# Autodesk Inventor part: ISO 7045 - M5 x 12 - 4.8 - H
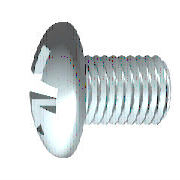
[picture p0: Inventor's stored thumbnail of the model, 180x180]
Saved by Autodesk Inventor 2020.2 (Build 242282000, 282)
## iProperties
Manager: www.cadconsulting.pl
Company: Fabian Stasiak CAD Consulting
Created: 2013-02
Part Number: ISO 7045 - M5 x 12 - 4.8 - H
Material: Stal nierdzewna 440C
Description: Śruba z łbem walcowym wypukłym z wgłębieniem krzyżowym
Document SubType Name: Modeling
Standard: ISO 7045
Designer: F.Stasiak
Standard Revision: 1994
Standards Organization: DIN
Language: pl-PL
Size Designation: M5 x 12 - 4.8 - H
Categories: <MemberInstance><Categories><Category DisplayName="Mocowania" InternalName="e4da775c-781d-43d5-af7c-5136215cf5a6" Mnemonic="FSTN"><Category DisplayName="Śruby"
Density: 7.75 g/cm^3
Appearance: Częściowo polerowana
IsCustomPart: 0
Author: F.Stasiak
Subject: Zbiór ćwiczeń. Autodesk Inventor 2020. Kurs podstawowy
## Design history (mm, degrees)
workplane "Work Plane3"
sketch "Szkic2"
  geometry: L1 (-6.543, 0)-(6.543, 0) reference; L2 (0, -6.543)-(0, 6.543) reference; L3 (0, 2.45)-(0, 0); L4 (0, 0)-(2.45, 0); L5 (0, 0)-(3.305, 3.305); L6 (0.415, 2.415)-(0.426, 0.744); L7 (2.415, 0.415)-(0.744, 0.426); L8 (0.415, -2.415)-(0.426, -0.744); L9 (2.415, -0.415)-(0.744, -0.426); L10 (-0.415, 2.415)-(-0.426, 0.744); L11 (-2.415, 0.415)-(-0.744, 0.426); L12 (-2.415, -0.415)-(-0.744, -0.426); L13 (-0.415, -2.415)-(-0.426, -0.744); A1 r 0.735 centre (0, 0) between (0.735, 0) and (0, 0.735); A2 r 2.45 centre (0, 0) between (2.45, 0) and (2.415, 0.415); A3 r 2.45 centre (0, 0) between (0.415, 2.415) and (0, 2.45); A4 r 2.45 centre (0, 0) between (2.415, 0.415) and (0.415, 2.415); A5 r 2.45 centre (0, 0) between (0, -2.45) and (0.415, -2.415); A6 r 2.45 centre (0, 0) between (0.415, -2.415) and (2.415, -0.415); A7 r 2.45 centre (0, 0) between (2.415, -0.415) and (2.45, 0); A8 r 2.45 centre (0, 0) between (-2.415, 0.415) and (-2.45, 0); A9 r 2.45 centre (0, 0) between (-0.415, 2.415) and (-2.415, 0.415); A10 r 2.45 centre (0, 0) between (0, 2.45) and (-0.415, 2.415); A11 r 2.45 centre (0, 0) between (-2.45, 0) and (-2.415, -0.415); A12 r 2.45 centre (0, 0) between (-2.415, -0.415) and (-0.415, -2.415); A13 r 2.45 centre (0, 0) between (-0.415, -2.415) and (0, -2.45); A14 r 0.858 centre (0, 0) between (0.858, 0) and (0, 0.858); A15 r 0.321 centre (0.746, 0.746) between (0.426, 0.744) and (0.744, 0.426); A16 r 0.321 centre (0.746, -0.746) between (0.744, -0.426) and (0.426, -0.744); A17 r 0.321 centre (-0.746, 0.746) between (-0.744, 0.426) and (-0.426, 0.744); A18 r 0.321 centre (-0.746, -0.746) between (-0.426, -0.744) and (-0.744, -0.426); 1 further point
  constraints: 38 point on circle, 22 end point, 19 symmetric about line, 18 centre point, 4 coincident, 3 collinear, 3 point on line, 3 tangent, 1 perpendicular, 21 other
  dimensions: "d4" = 45 deg angle of L5 L4; "d5" = 1.47 diameter of A1 (= 0.3 x SDM); "d6" = 4.9 diameter of A4 (= SDM); "d7" = 0.415 distance from line of L6.start L3 (= 0.5 x SBR); "d14" = 1.715 diameter of A14 (= 0.35 x SDM)
extrude "Szczelina" join sketch "Szkic2" taper "d15" = 5 deg; stored distance "d54" = 10
revolve "Wycięcie" stored, may be unused: angle "d56" = 90 deg
revolve "Bryła" stored, may be unused: angle "d18" = 90 deg
workplane "Work Plane1"
body "Solid1"
sketch "Szkic1"
  geometry: L1 (12, 0)-(12, 2.5); L2 (12, 2.5)-(1.6, 2.5); L3 (3.962, 5.08)-(3.962, 5.08); L4 (-3.7, 0)-(-3.7, 4.621); L5 (-3.367, 2.284)-(-1.526, 1.366); L6 (-1.526, 1.366)-(-0.8, 0); L7 (-0.8, 0)-(12, 0); L8 (-7.281, 0)-(15.213, 0) reference; L9 (0, -1.016)-(0, 6.096) reference; L10 (-3.367, 2.284)-(-3.7, 2.45); L11 (-2.193, 4.673)-(-3.7, 4.621); L12 (-2.193, 4.673)-(0, 4.75); L13 (0, 4.75)-(0, 2.483); L14 (0.2, 2.283)-(1.109, 2.283); L15 (1.109, 2.283)-(1.6, 2.5); L16 (1.6, 2.5)-(0, 2.5); A1 r 8 centre (4.3, 0) between (-2.193, 4.673) and (-3.7, 0); A2 r 0.2 centre (0.2, 2.483) between (0, 2.483) and (0.2, 2.283); 1 further point
  constraints: 28 end point, 7 point on line, 6 point on circle, 4 collinear, 3 parallel, 3 tangent, 2 centre point, 2 perpendicular, 1 horizontal
  dimensions: "d1" = 5 diameter of L2 L7 (= GD); "d2" = 2.9 distance from line of L6.end L4 (= STI); "d11" = 4.9 diameter of L10.end L7 (= SDM); "d12" = 62 deg angle of L6 L7; "d13" = 26.5 deg angle of L5 L7; "d17" = 9.5 diameter of L12.end L7 (= KOD); "d19" = 2 deg angle of L12 L7 (= KEWI); "d20" = 3.7 distance between parallel lines of L4 L13 (= KOH); "d21" = 8 radius of A1 (= KR); "d23" = 4.56699 diameter of L14 L7 (= BDM); "d24" = 10.4 distance of L1.end L2.end (= GEL); "d25" = 0.49076 horizontal distance of L14.end L2.end (= GAL); "d28" = 12 distance between parallel lines of L1 L13 (= NLG); "d81" = 0.2 radius of A2 (= R)
fillet "Zaokrąglenie1" dims "d29" = 1.6 (= RR)
fillet "Zaokrąglenie2" dims "d16" = 0.166 (= 0.2 x SBR)
feature "Gwint" dims "d8" = 10.4 (= GEL), "d9" = 0
chamfer "Faza1" distance "d26" = 0.49076 (= -0.5 x SPD + 0.5 x GD); stored, may be unused: second distance "d27" = 0.49086 (computed from GUL), angle "d78" = 45 deg
other parameters: "GD" = 5 [user parameter; used in 2 equation terms], "NLG" = 12 [user parameter; used in 1 equation term], "GEL" = 10.4 [user parameter; used in 2 equation terms], "KOD" = 9.5 [user parameter; used in 1 equation term], "KOH" = 3.7 [user parameter; used in 2 equation terms], "SDM" = 4.9 [user parameter; used in 4 equation terms], "STI" = 2.9 [user parameter; used in 1 equation term], "SBR" = 0.83 [user parameter; used in 2 equation terms], "GAL" = 0.49076 (= 0.61345 x PTC) [user parameter; used in 1 equation term], "SPD" = 4.01848 (= NND - 1.2269 x PTC) [user parameter; used in 1 equation term], "KEWI" = 2 deg [user parameter; used in 1 equation term], "d3" = -3.7 (= -KOH), "d10" = 0, "KR" = 8 [user parameter; used in 1 equation term], "BDM" = 4.56699 [user parameter; used in 1 equation term], "GUL" = 0.49076 (= 0.61345 x PTC) [user parameter; used in 1 equation term], "RR" = 1.6 [user parameter; used in 1 equation term], "d79" = 0, "d80" = 0, "R" = 0.2 [user parameter; used in 1 equation term], "PTC" = 0.8 [user parameter; used in 5 equation terms], "THREADDIA" = 5 [user parameter; used in 1 equation term], "TOA" = 30 deg [user parameter], "TPU" = 12.5 (computed from PTC) [user parameter], "NND" = 5 [user parameter; used in 1 equation term], "GD1" = 4.01848 (= THREADDIA - 1.2269 x PTC) [user parameter]
